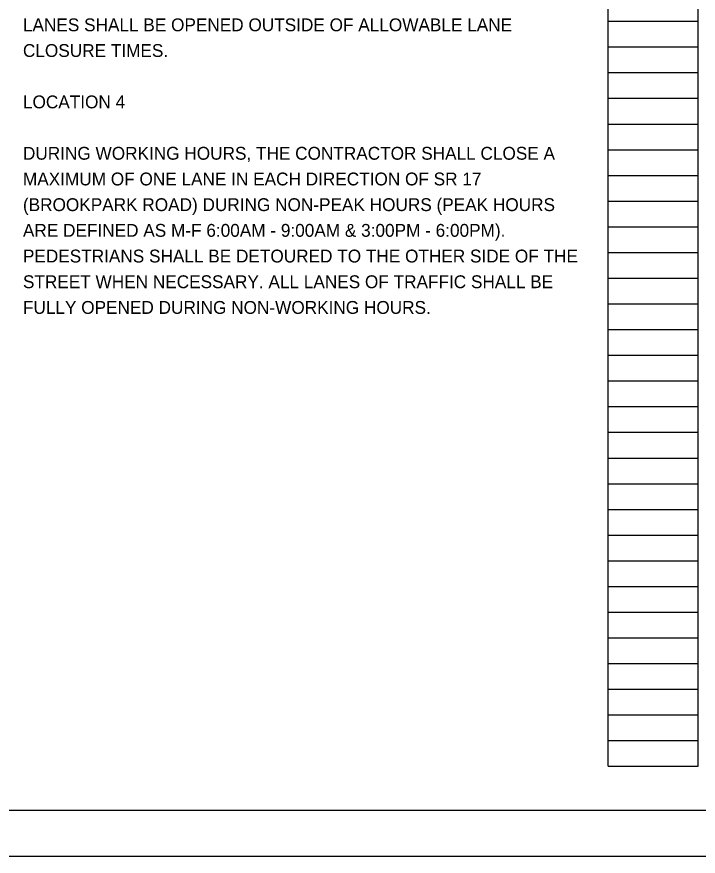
# Model space of a CAD drawing. Extents: x -0.2 to 33.8, y 0.1 to 22.1.
# Drawn here: x 17.04 to 24.46, y 0.12 to 9.27 of the extents above; entities that cross this region are included whole.
import ezdxf

# ---------------------------------------------------------------- set-up
doc = ezdxf.new("R2010")
doc.units = 0
for name, color, linetype in [('SH_Border', 7, 'Continuous'), ('SH_Cut_Line', 7, 'Continuous'), ('SH_Data', 7, 'Continuous'), ('SH_Text', 7, 'Continuous')]:
    doc.layers.add(name, color=color, linetype=linetype)

msp = doc.modelspace()

# ---------------------------------------------------------------- linework, layer by layer
at = {"layer": 'SH_Border'}
msp.add_lwpolyline([(1.2977, 21.6208), (33.2977, 21.6208), (33.2977, 0.6208), (1.2977, 0.6208)], close=True, dxfattribs=at)
at = {"layer": 'SH_Cut_Line'}
msp.add_lwpolyline([(-0.2023, 0.1208), (33.7977, 0.1208), (33.7977, 22.1208), (-0.2023, 22.1208)], close=True, dxfattribs=at)
at = {"layer": 'SH_Data'}
for p, q in [((23.4777, 1.1008), (23.4777, 21.2608)), ((24.4577, 1.1008), (24.4577, 21.2608)), ((23.4777, 9.2208), (24.4577, 9.2208)), ((23.4777, 8.9408), (24.4577, 8.9408)), ((23.4777, 8.6608), (24.4577, 8.6608)), ((23.4777, 8.3808), (24.4577, 8.3808)), ((23.4777, 8.1008), (24.4577, 8.1008)), ((23.4777, 7.8208), (24.4577, 7.8208)), ((23.4777, 7.5408), (24.4577, 7.5408)), ((23.4777, 7.2608), (24.4577, 7.2608)), ((23.4777, 6.9808), (24.4577, 6.9808)), ((23.4777, 6.7008), (24.4577, 6.7008)), ((23.4777, 6.4208), (24.4577, 6.4208)), ((23.4777, 6.1408), (24.4577, 6.1408)), ((23.4777, 5.8608), (24.4577, 5.8608)), ((23.4777, 5.5808), (24.4577, 5.5808)), ((23.4777, 5.3008), (24.4577, 5.3008)), ((23.4777, 5.0208), (24.4577, 5.0208)), ((23.4777, 4.7408), (24.4577, 4.7408)), ((23.4777, 4.4608), (24.4577, 4.4608)), ((23.4777, 4.1808), (24.4577, 4.1808)), ((23.4777, 3.9008), (24.4577, 3.9008)), ((23.4777, 3.6208), (24.4577, 3.6208)), ((23.4777, 3.3408), (24.4577, 3.3408)), ((23.4777, 3.0608), (24.4577, 3.0608)), ((23.4777, 2.7808), (24.4577, 2.7808)), ((23.4777, 2.5008), (24.4577, 2.5008)), ((23.4777, 2.2208), (24.4577, 2.2208)), ((23.4777, 1.9408), (24.4577, 1.9408)), ((23.4777, 1.6608), (24.4577, 1.6608)), ((23.4777, 1.3808), (24.4577, 1.3808)), ((23.4777, 1.1008), (24.4577, 1.1008))]:
    msp.add_line(p, q, dxfattribs=at)

# ---------------------------------------------------------------- texts
at = {"layer": 'SH_Text'}
for s, p in [('LANES SHALL BE OPENED OUTSIDE OF ALLOWABLE LANE ', (17.1048, 9.1118)), ('CLOSURE TIMES.', (17.1048, 8.8318)), ('LOCATION 4', (17.1048, 8.2718)), ('DURING WORKING HOURS, THE CONTRACTOR SHALL CLOSE A ', (17.1048, 7.7118)), ('MAXIMUM OF ONE LANE IN EACH DIRECTION OF SR 17 ', (17.1048, 7.4318)), ('(BROOKPARK ROAD) DURING NON-PEAK HOURS (PEAK HOURS ', (17.1048, 7.1518)), ('ARE DEFINED AS M-F 6:00AM - 9:00AM & 3:00PM - 6:00PM). ', (17.1048, 6.8718)), ('PEDESTRIANS SHALL BE DETOURED TO THE OTHER SIDE OF THE ', (17.1048, 6.5918)), ('STREET WHEN NECESSARY. ALL LANES OF TRAFFIC SHALL BE ', (17.1048, 6.3118)), ('FULLY OPENED DURING NON-WORKING HOURS.', (17.1048, 6.0318))]:
    msp.add_text(s, height=0.14, dxfattribs=at).set_placement(p)

doc.saveas('drawing.dxf')
